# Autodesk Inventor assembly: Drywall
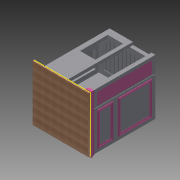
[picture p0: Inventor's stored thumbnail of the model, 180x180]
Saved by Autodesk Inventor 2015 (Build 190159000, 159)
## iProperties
Created: 2015-04
Part Number: Drywall
Document SubType Name: Assembly
Designer: suporte
_SolveAssemblyDoc: Frame Generator Solve Assembly
_Version: 15.0.0
Author: suporte
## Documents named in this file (69)
- C:\Users\suporte\Desktop\Kévin\WorldSkills SP\Grupo Kazuo\21\Arquivos Edição\Arquivos Inventor\Drywall.iam
- C:\Users\suporte\Desktop\Kévin\WorldSkills SP\Grupo Kazuo\21\Arquivos Edição\Arquivos Inventor\Base.ipt
- C:\Users\suporte\Desktop\Kévin\WorldSkills SP\Grupo Kazuo\21\Arquivos Edição\Arquivos Inventor\Moldura 1.ipt
- C:\Users\suporte\Desktop\Kévin\WorldSkills SP\Grupo Kazuo\21\Arquivos Edição\Arquivos Inventor\Moldura 2.ipt
- C:\Users\suporte\Desktop\Kévin\WorldSkills SP\Grupo Kazuo\21\Arquivos Edição\Arquivos Inventor\Rodapé.ipt
- C:\Users\suporte\Desktop\Kévin\WorldSkills SP\Grupo Kazuo\21\Arquivos Edição\Arquivos Inventor\Estrutura Metálica.ipt
- C:\Users\suporte\Desktop\Kévin\WorldSkills SP\Grupo Kazuo\21\Arquivos Edição\Arquivos Inventor\Drywall\Frame\Frame0001.iam
- C:\Users\suporte\Desktop\Kévin\WorldSkills SP\Grupo Kazuo\21\Arquivos Edição\Arquivos Inventor\Canto Madeira.ipt
- C:\Users\suporte\Desktop\Kévin\WorldSkills SP\Grupo Kazuo\21\Arquivos Edição\Arquivos Inventor\Canto Madeira 2.ipt
- C:\Users\suporte\Desktop\Kévin\WorldSkills SP\Grupo Kazuo\21\Arquivos Edição\Arquivos Inventor\Placa 1.ipt
- C:\Users\suporte\Desktop\Kévin\WorldSkills SP\Grupo Kazuo\21\Arquivos Edição\Arquivos Inventor\Placa 2.ipt
- C:\Users\suporte\Desktop\Kévin\WorldSkills SP\Grupo Kazuo\21\Arquivos Edição\Arquivos Inventor\Placa 3.ipt
- C:\Users\suporte\Desktop\Kévin\WorldSkills SP\Grupo Kazuo\21\Arquivos Edição\Arquivos Inventor\Placa 4.ipt
- C:\Users\suporte\Desktop\Kévin\WorldSkills SP\Grupo Kazuo\21\Arquivos Edição\Arquivos Inventor\Placa 5.ipt
- C:\Users\suporte\Desktop\Kévin\WorldSkills SP\Grupo Kazuo\21\Arquivos Edição\Arquivos Inventor\Placa 6.ipt
- C:\Users\suporte\Desktop\Kévin\WorldSkills SP\Grupo Kazuo\21\Arquivos Edição\Arquivos Inventor\Placa 7.ipt
- C:\Users\suporte\Desktop\Kévin\WorldSkills SP\Grupo Kazuo\21\Arquivos Edição\Arquivos Inventor\Placa 8.ipt
- C:\Users\suporte\Desktop\Kévin\WorldSkills SP\Grupo Kazuo\21\Arquivos Edição\Arquivos Inventor\Placa 9.ipt
- C:\Users\suporte\Desktop\Kévin\WorldSkills SP\Grupo Kazuo\21\Arquivos Edição\Arquivos Inventor\Placa 10.ipt
- C:\Users\suporte\Desktop\Kévin\WorldSkills SP\Grupo Kazuo\21\Arquivos Edição\Arquivos Inventor\Placa 11.ipt
- C:\Users\suporte\Desktop\Kévin\WorldSkills SP\Grupo Kazuo\21\Arquivos Edição\Arquivos Inventor\Placa 12.ipt
- C:\Users\suporte\Desktop\Kévin\WorldSkills SP\Grupo Kazuo\21\Arquivos Edição\Arquivos Inventor\Placa 13.ipt
- C:\Users\suporte\Desktop\Kévin\WorldSkills SP\Grupo Kazuo\21\Arquivos Edição\Arquivos Inventor\Placa 14.ipt
- C:\Users\suporte\Desktop\Kévin\WorldSkills SP\Grupo Kazuo\21\Arquivos Edição\Arquivos Inventor\Placa 15.ipt
- C:\Users\suporte\Desktop\Kévin\WorldSkills SP\Grupo Kazuo\21\Arquivos Edição\Arquivos Inventor\Placa 16.ipt
- C:\Users\suporte\Desktop\Kévin\WorldSkills SP\Grupo Kazuo\21\Arquivos Edição\Arquivos Inventor\Placa 18.ipt
- C:\Users\suporte\Desktop\Kévin\WorldSkills SP\Grupo Kazuo\21\Arquivos Edição\Arquivos Inventor\Placa 19.ipt
- C:\Users\suporte\Desktop\Kévin\WorldSkills SP\Grupo Kazuo\21\Arquivos Edição\Arquivos Inventor\Placa 20.ipt
- C:\Users\suporte\Desktop\Kévin\WorldSkills SP\Grupo Kazuo\21\Arquivos Edição\Arquivos Inventor\Placa 21.ipt
- C:\Users\suporte\Desktop\Kévin\WorldSkills SP\Grupo Kazuo\21\Arquivos Edição\Arquivos Inventor\Placa 22.ipt
- C:\Users\suporte\Desktop\Kévin\WorldSkills SP\Grupo Kazuo\21\Arquivos Edição\Arquivos Inventor\Placa 23.ipt
- C:\Users\suporte\Desktop\Kévin\WorldSkills SP\Grupo Kazuo\21\Arquivos Edição\Arquivos Inventor\Placa 24.ipt
- C:\Users\suporte\Desktop\Kévin\WorldSkills SP\Grupo Kazuo\21\Arquivos Edição\Arquivos Inventor\Placa 25.ipt
- C:\Users\suporte\Desktop\Kévin\WorldSkills SP\Grupo Kazuo\21\Arquivos Edição\Arquivos Inventor\Placa 26.ipt
- C:\Users\suporte\Desktop\Kévin\WorldSkills SP\Grupo Kazuo\21\Arquivos Edição\Arquivos Inventor\Placa 27.ipt
- C:\Users\suporte\Desktop\Kévin\WorldSkills SP\Grupo Kazuo\21\Arquivos Edição\Arquivos Inventor\Placa Lã 1.ipt
- C:\Users\suporte\Desktop\Kévin\WorldSkills SP\Grupo Kazuo\21\Arquivos Edição\Arquivos Inventor\Placa Lã 2.ipt
- C:\Users\suporte\Desktop\Kévin\WorldSkills SP\Grupo Kazuo\21\Arquivos Edição\Arquivos Inventor\Placa Lã 3.ipt
- C:\Users\suporte\Desktop\Kévin\WorldSkills SP\Grupo Kazuo\21\Arquivos Edição\Arquivos Inventor\Frame Bearing.ipt
- C:\Users\suporte\Desktop\Kévin\WorldSkills SP\Grupo Kazuo\21\Arquivos Edição\Arquivos Inventor\Placa Lã 4.ipt
- C:\Users\suporte\Desktop\Kévin\WorldSkills SP\Grupo Kazuo\21\Arquivos Edição\Arquivos Inventor\Placa 28.ipt
- C:\Users\suporte\Desktop\Kévin\WorldSkills SP\Grupo Kazuo\21\Arquivos Edição\Arquivos Inventor\Placa 29.ipt
- C:\Users\suporte\Desktop\Kévin\WorldSkills SP\Grupo Kazuo\21\Arquivos Edição\Arquivos Inventor\Placa 30.ipt
- C:\Users\suporte\Desktop\Kévin\WorldSkills SP\Grupo Kazuo\21\Arquivos Edição\Arquivos Inventor\Placa 31.ipt
- C:\Users\suporte\Desktop\Kévin\WorldSkills SP\Grupo Kazuo\21\Arquivos Edição\Arquivos Inventor\Placa 32.ipt
- C:\Users\suporte\Desktop\Kévin\WorldSkills SP\Grupo Kazuo\21\Arquivos Edição\Arquivos Inventor\Placa 33.ipt
- C:\Users\suporte\Desktop\Kévin\WorldSkills SP\Grupo Kazuo\21\Arquivos Edição\Arquivos Inventor\Placa 34.ipt
- C:\Users\suporte\Desktop\Kévin\WorldSkills SP\Grupo Kazuo\21\Arquivos Edição\Arquivos Inventor\Placa 35.ipt
- C:\Users\suporte\Desktop\Kévin\WorldSkills SP\Grupo Kazuo\21\Arquivos Edição\Arquivos Inventor\Placa 36.ipt
- C:\Users\suporte\Desktop\Kévin\WorldSkills SP\Grupo Kazuo\21\Arquivos Edição\Arquivos Inventor\Detalhe Pintado.ipt
- C:\Users\suporte\Desktop\Kévin\WorldSkills SP\Grupo Kazuo\21\Arquivos Edição\Arquivos Inventor\Placa Teto.ipt
- C:\Users\suporte\Desktop\Kévin\WorldSkills SP\Grupo Kazuo\21\Arquivos Edição\Arquivos Inventor\Placa 37.ipt
- C:\Users\suporte\Desktop\Kévin\WorldSkills SP\Grupo Kazuo\21\Arquivos Edição\Arquivos Inventor\Placa 38.ipt
- C:\Users\suporte\Desktop\Kévin\WorldSkills SP\Grupo Kazuo\21\Arquivos Edição\Arquivos Inventor\Placa 39.ipt
- C:\Users\suporte\Desktop\Kévin\WorldSkills SP\Grupo Kazuo\21\Arquivos Edição\Arquivos Inventor\Placa 40.ipt
- C:\Users\suporte\Desktop\Kévin\WorldSkills SP\Grupo Kazuo\21\Arquivos Edição\Arquivos Inventor\Placa 42.ipt
- C:\Users\suporte\Desktop\Kévin\WorldSkills SP\Grupo Kazuo\21\Arquivos Edição\Arquivos Inventor\Placa 43.ipt
- C:\Users\suporte\Desktop\Kévin\WorldSkills SP\Grupo Kazuo\21\Arquivos Edição\Arquivos Inventor\Placa 44.ipt
- C:\Users\suporte\Desktop\Kévin\WorldSkills SP\Grupo Kazuo\21\Arquivos Edição\Arquivos Inventor\Placa 45.ipt
- C:\Users\suporte\Desktop\Kévin\WorldSkills SP\Grupo Kazuo\21\Arquivos Edição\Arquivos Inventor\Placa 46.ipt
- C:\Users\suporte\Desktop\Kévin\WorldSkills SP\Grupo Kazuo\21\Arquivos Edição\Arquivos Inventor\Placa 47.ipt
- C:\Users\suporte\Desktop\Kévin\WorldSkills SP\Grupo Kazuo\21\Arquivos Edição\Arquivos Inventor\Placa 48.ipt
- C:\Users\suporte\Desktop\Kévin\WorldSkills SP\Grupo Kazuo\21\Arquivos Edição\Arquivos Inventor\Placa 49.ipt
- C:\Users\suporte\Desktop\Kévin\WorldSkills SP\Grupo Kazuo\21\Arquivos Edição\Arquivos Inventor\Placa 50.ipt
- C:\Users\suporte\Desktop\Kévin\WorldSkills SP\Grupo Kazuo\21\Arquivos Edição\Arquivos Inventor\Placa 51.ipt
- C:\Users\suporte\Desktop\Kévin\WorldSkills SP\Grupo Kazuo\21\Arquivos Edição\Arquivos Inventor\placa 52.ipt
- C:\Users\suporte\Desktop\Kévin\WorldSkills SP\Grupo Kazuo\21\Arquivos Edição\Arquivos Inventor\placa 53.ipt
- C:\Users\suporte\Desktop\Kévin\WorldSkills SP\Grupo Kazuo\21\Arquivos Edição\Arquivos Inventor\Placa 54.ipt
- C:\Users\suporte\Desktop\Kévin\WorldSkills SP\Grupo Kazuo\21\Arquivos Edição\Arquivos Inventor\Placa 55.ipt
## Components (87 placed, 68 different names)
1. Base:1 — Mate:2, Mate:3, Mate:4, Mate:5, Flush:4, Flush:5, Mate:6, Mate:7, Flush:6, Flush:7, Flush:8, Flush:9, Flush:13, Mate:8, Flush:15, Mate:11, Flush:18, Flush:19, Flush:32, Flush:33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
2. Moldura 1:1 — Flush:1, Flush:2, Mate:1, Flush:4
3. Moldura 2:1 — Flush:1, Flush:2, Mate:1, Flush:3, Mate:5
4. Rodapé:1 — Mate:2, Mate:3, Mate:4, Flush:3, Mate:76
5. Estrutura Metálica:1 — Flush:5, Mate:6, Mate:7, Mate:78
6. Frame0001:1 [sub-assembly] — Flush:10, Flush:11, Flush:12, Mate:9, Flush:14, Mate:12, Flush:16, Flush:17, Mate:15, Mate:17, Flush:22, Mate:18, Flush:27, Flush:28, Mate:22, Flush:30, Mate:25, Mate:28, Mate:30, Mate:32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
7. Canto Madeira:1 — Flush:6, Flush:7, Mate:33, Mate:34, Mate:35
8. Canto Madeira 2:1 — Flush:8, Flush:9
9. Placa 1:1 — Flush:10, Flush:11, Mate:14, Flush:20, Flush:21, Flush:24, Mate:20, Mate:23, Mate:24
10. Placa 2:1 — Flush:12, Flush:13, Mate:10, Mate:14, Flush:20, Flush:21
11. Placa 1:2 — Mate:8, Mate:9, Mate:10, Mate:13, Mate:27
12. Placa 3:1 — Flush:14, Flush:15, Mate:16, Flush:26, Mate:19, Mate:20
13. Placa 3:2 — Mate:11, Mate:12, Mate:13, Mate:29
14. Placa 4:1 — Flush:16, Flush:17, Mate:15, Mate:16, Mate:17, Flush:23, Mate:21
15. Placa 5:1 — Flush:18, Flush:19, Flush:25, Flush:26, Mate:19, Mate:31
16. Placa 6:1 — Flush:22, Flush:23, Flush:24
17. Placa 6:2 — Flush:25, Mate:18, Mate:21, Flush:29
18. Placa 7:1 — Flush:27, Flush:28, Mate:22, Flush:29, Mate:23, Flush:31, Mate:26
19. Placa 8:1 — Flush:30, Flush:31, Mate:24
20. Placa 8:2 — Mate:25, Mate:26, Mate:27
21. Placa 9:1 — Flush:32, Flush:33, Mate:30, Mate:31, Mate:37
22. Placa 10:1 — Flush:34, Flush:35, Mate:28, Mate:29, Mate:35
23. Placa 11:1 — Flush:36, Flush:37, Mate:32, Mate:33, Mate:34
24. Placa 12:1 — Flush:38, Flush:39, Mate:36, Mate:38, Mate:44, Flush:58
25. Placa 13:1 — Flush:40, Flush:41, Mate:37, Mate:40, Flush:47, Flush:48
26. Placa 14:1 — Flush:42, Flush:43, Mate:38, Mate:39
27. Placa 15:1 — Flush:44, Flush:45, Mate:40
28. Placa 16:1 — Flush:46, Flush:47, Flush:48
29. Placa 18:1 — Flush:51, Flush:52, Mate:41, Flush:54, Flush:57
30. Placa 19:1 — Flush:55, Flush:56, Mate:42, Flush:57, Flush:62, Mate:47
31. Placa 16:2 — Mate:43, Mate:44, Flush:58, Mate:46, Flush:59
32. Placa 19:2 — Mate:45, Mate:46, Flush:59, Mate:50
33. Placa 20:1 — Flush:60, Flush:61, Flush:62, Mate:47, Mate:79, Mate:87
34. Placa 21:1 — Flush:63, Flush:64, Mate:48, Flush:67, Mate:54, Mate:80, Mate:86
35. Placa 22:1 — Flush:65, Flush:66, Mate:49, Mate:50, Mate:52
36. Placa 23:1 — Flush:68, Flush:69, Mate:51, Mate:52
37. Placa 24:1 — Flush:70, Flush:71, Flush:72, Mate:53, Flush:75, Flush:140, Flush:141
38. Placa 25:1 — Flush:73, Flush:74, Mate:54, Flush:75
39. Placa 26:1 — Flush:76, Flush:77, Mate:56, Flush:80, Mate:58, Mate:74, Flush:118
40. Placa 26:2 — Mate:55, Flush:78, Flush:79, Mate:57, Flush:83, Mate:69, Flush:112
41. Placa 27:1 — Flush:81, Flush:82, Mate:58, Flush:85
42. Placa 27:2 — Mate:57, Flush:83, Flush:84, Mate:71, Flush:113, Mate:75
43. Placa Lã 1:1 — Flush:86, Flush:87
44. Placa Lã 2:1 — Flush:88, Flush:89
45. Placa Lã 3:1 — Flush:90, Flush:91
46. Frame Bearing:1 — Flush:92, Flush:93, Flush:94
47. Frame Bearing:2 — Mate:59, Mate:60, Flush:94, Mate:62, Mate:63
48. Placa Lã 4:1 — Flush:95, Flush:96
49. Placa 28:1 — Flush:97
50. Placa 28:2 — Mate:61, Mate:62, Mate:63
51. Placa 29:1 — Flush:98, Flush:99
52. Placa 30:1 — Flush:100, Flush:101
53. Placa 31:1 — Flush:102, Flush:103
54. Placa 32:1 — Flush:104, Flush:105
55. Placa 33:1 — Flush:106, Flush:107
56. Placa 34:1 — Flush:108, Flush:109, Flush:122, Flush:123
57. Placa 30:2 — Mate:66
58. Placa 31:2 — Mate:68, Mate:69, Flush:112
59. Placa 34:2 — Mate:70, Mate:71, Flush:113, Mate:73, Flush:114
60. Placa 33:2 — Mate:72, Mate:73, Flush:114
61. Placa 35:1 — Flush:115, Flush:116, Flush:117, Mate:74, Flush:118, Flush:120, Flush:121
62. Placa 36:1 — Flush:119, Flush:120, Flush:121
63. Detalhe Pintado:1 — Flush:122, Flush:123, Mate:75, Mate:76
64. Placa Teto:1 — Mate:77, Flush:124, Flush:125
65. Placa 37:1 — Flush:124, Flush:125, Flush:126, Flush:127, Flush:134, Flush:135, Flush:136, Flush:137
66. Placa 38:1 — Flush:126, Flush:127, Flush:128, Flush:129, Flush:132, Flush:133, Flush:138, Flush:139
67. Placa 39:1 — Flush:128, Flush:129, Flush:130, Flush:131
68. Placa 40:1 — Flush:130, Flush:131
69. Placa 42:1 — Flush:132, Flush:133
70. Placa 43:1 — Flush:134, Flush:135
71. Placa 44:1 — Flush:136, Flush:137
72. Placa 45:1 — Flush:138, Flush:139
73. Placa 46:1 — Flush:140, Flush:141, Flush:142, Flush:143, Flush:144, Flush:145, Flush:147
74. Placa 47:1 — Flush:142, Flush:143, Flush:148, Flush:149, Flush:152, Flush:153, Flush:154, Flush:155
75. Placa 48:1 — Flush:144, Flush:145, Flush:146
76. Placa 49:1 — Flush:146, Flush:147
77. Placa 50:1 — Flush:148, Flush:149, Flush:150, Flush:151
78. Placa 51:1 — Flush:150, Flush:151
79. placa 52:1 — Flush:152, Flush:153
80. placa 53:1 — Flush:154, Flush:155, Flush:156, Flush:157, Flush:158, Flush:159
81. Placa 54:1 — Flush:156, Flush:157
82. Placa 55:1 — Flush:158, Flush:159, Mate:81
83. placa 53:2 — Mate:79, Mate:80, Mate:81, Mate:88
84. placa 53:3 — Mate:82, Flush:160, Flush:161, Mate:83, Flush:162, Flush:163, Mate:88
85. placa 53:4 — Mate:85, Flush:163, Flush:164, Mate:86, Mate:87
86. Placa 54:2 — Mate:82, Flush:160, Flush:161, Mate:84
87. Placa 55:2 — Mate:83, Flush:162, Mate:84, Mate:85, Flush:164
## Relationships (244: Flush 159, Mate 85)
- Flush:1: Moldura 1:1 ↔ Moldura 2:1
- Flush:2: Moldura 1:1 ↔ Moldura 2:1
- Mate:1: Moldura 1:1 ↔ Moldura 2:1
- Mate:2: Base:1 ↔ Rodapé:1
- Mate:3: Base:1 ↔ Rodapé:1
- Mate:4: Base:1 ↔ Rodapé:1
- Flush:3: Moldura 2:1 ↔ Rodapé:1
- Mate:5: Base:1 ↔ Moldura 2:1
- Flush:4: Base:1 ↔ Moldura 1:1
- Flush:5: Base:1 ↔ Estrutura Metálica:1
- Mate:6: Base:1 ↔ Estrutura Metálica:1
- Mate:7: Base:1 ↔ Estrutura Metálica:1
- Flush:6: Base:1 ↔ Canto Madeira:1
- Flush:7: Base:1 ↔ Canto Madeira:1
- Flush:8: Base:1 ↔ Canto Madeira 2:1
- Flush:9: Base:1 ↔ Canto Madeira 2:1
- Flush:10: Frame0001:1 ↔ Placa 1:1
- Flush:11: Frame0001:1 ↔ Placa 1:1
- Flush:12: Frame0001:1 ↔ Placa 2:1
- Flush:13: Base:1 ↔ Placa 2:1
- Mate:8: Base:1 ↔ Placa 1:2
- Mate:9: Frame0001:1 ↔ Placa 1:2
- Mate:10: Placa 2:1 ↔ Placa 1:2
- Flush:14: Frame0001:1 ↔ Placa 3:1
- Flush:15: Base:1 ↔ Placa 3:1
- Mate:11: Base:1 ↔ Placa 3:2
- Mate:12: Frame0001:1 ↔ Placa 3:2
- Mate:13: Placa 1:2 ↔ Placa 3:2
- Flush:16: Frame0001:1 ↔ Placa 4:1
- Flush:17: Frame0001:1 ↔ Placa 4:1
- Flush:18: Base:1 ↔ Placa 5:1
- Flush:19: Base:1 ↔ Placa 5:1
- Mate:14: Placa 1:1 ↔ Placa 2:1
- Flush:20: Placa 1:1 ↔ Placa 2:1
- Flush:21: Placa 1:1 ↔ Placa 2:1
- Mate:15: Frame0001:1 ↔ Placa 4:1
- Mate:16: Placa 3:1 ↔ Placa 4:1
- Mate:17: Frame0001:1 ↔ Placa 4:1
- Flush:22: Frame0001:1 ↔ Placa 6:1
- Flush:23: Placa 4:1 ↔ Placa 6:1
- Flush:24: Placa 1:1 ↔ Placa 6:1
- Flush:25: Placa 5:1 ↔ Placa 6:2
- Mate:18: Frame0001:1 ↔ Placa 6:2
- Flush:26: Placa 3:1 ↔ Placa 5:1
- Mate:19: Placa 3:1 ↔ Placa 5:1
- Mate:20: Placa 1:1 ↔ Placa 3:1
- Mate:21: Placa 4:1 ↔ Placa 6:2
- Flush:27: Frame0001:1 ↔ Placa 7:1
- Flush:28: Frame0001:1 ↔ Placa 7:1
- Mate:22: Frame0001:1 ↔ Placa 7:1
- Flush:29: Placa 6:2 ↔ Placa 7:1
- Mate:23: Placa 1:1 ↔ Placa 7:1
- Flush:30: Frame0001:1 ↔ Placa 8:1
- Flush:31: Placa 7:1 ↔ Placa 8:1
- Mate:24: Placa 1:1 ↔ Placa 8:1
- Mate:25: Frame0001:1 ↔ Placa 8:2
- Mate:26: Placa 7:1 ↔ Placa 8:2
- Mate:27: Placa 1:2 ↔ Placa 8:2
- Flush:32: Base:1 ↔ Placa 9:1
- Flush:33: Base:1 ↔ Placa 9:1
- Flush:34: Base:1 ↔ Placa 10:1
- Flush:35: Base:1 ↔ Placa 10:1
- Mate:28: Frame0001:1 ↔ Placa 10:1
- Mate:29: Placa 3:2 ↔ Placa 10:1
- Mate:30: Frame0001:1 ↔ Placa 9:1
- Mate:31: Placa 5:1 ↔ Placa 9:1
- Flush:36: Base:1 ↔ Placa 11:1
- Flush:37: Base:1 ↔ Placa 11:1
- Mate:32: Frame0001:1 ↔ Placa 11:1
- Mate:33: Canto Madeira:1 ↔ Placa 11:1
- Mate:34: Canto Madeira:1 ↔ Placa 11:1
- Mate:35: Canto Madeira:1 ↔ Placa 10:1
- Flush:38: Frame0001:1 ↔ Placa 12:1
- Flush:39: Base:1 ↔ Placa 12:1
- Mate:36: Frame0001:1 ↔ Placa 12:1
- Flush:40: Frame0001:1 ↔ Placa 13:1
- Flush:41: Base:1 ↔ Placa 13:1
- Mate:37: Placa 9:1 ↔ Placa 13:1
- Flush:42: Base:1 ↔ Placa 14:1
- Flush:43: Base:1 ↔ Placa 14:1
- Mate:38: Placa 12:1 ↔ Placa 14:1
- Mate:39: Frame0001:1 ↔ Placa 14:1
- Flush:44: Frame0001:1 ↔ Placa 15:1
- Flush:45: Frame0001:1 ↔ Placa 15:1
- Mate:40: Placa 13:1 ↔ Placa 15:1
- Flush:46: Frame0001:1 ↔ Placa 16:1
- Flush:47: Placa 13:1 ↔ Placa 16:1
- Flush:48: Placa 13:1 ↔ Placa 16:1
- Flush:51: Base:1 ↔ Placa 18:1
- Flush:52: Base:1 ↔ Placa 18:1
- Mate:41: Frame0001:1 ↔ Placa 18:1
- Flush:54: Frame0001:1 ↔ Placa 18:1
- Flush:55: Base:1 ↔ Placa 19:1
- Flush:56: Base:1 ↔ Placa 19:1
- Mate:42: Frame0001:1 ↔ Placa 19:1
- Flush:57: Placa 18:1 ↔ Placa 19:1
- Mate:43: Frame0001:1 ↔ Placa 16:2
- Mate:44: Placa 12:1 ↔ Placa 16:2
- Flush:58: Placa 12:1 ↔ Placa 16:2
- Mate:45: Frame0001:1 ↔ Placa 19:2
- Mate:46: Placa 16:2 ↔ Placa 19:2
- Flush:59: Placa 16:2 ↔ Placa 19:2
- Flush:60: Base:1 ↔ Placa 20:1
- Flush:61: Base:1 ↔ Placa 20:1
- Flush:62: Placa 19:1 ↔ Placa 20:1
- Mate:47: Placa 19:1 ↔ Placa 20:1
- Flush:63: Base:1 ↔ Placa 21:1
- Flush:64: Base:1 ↔ Placa 21:1
- Flush:65: Base:1 ↔ Placa 22:1
- Flush:66: Base:1 ↔ Placa 22:1
- Mate:48: Frame0001:1 ↔ Placa 21:1
- Flush:67: Frame0001:1 ↔ Placa 21:1
- Mate:49: Frame0001:1 ↔ Placa 22:1
- Mate:50: Placa 19:2 ↔ Placa 22:1
- Flush:68: Base:1 ↔ Placa 23:1
- Flush:69: Base:1 ↔ Placa 23:1
- Mate:51: Frame0001:1 ↔ Placa 23:1
- Mate:52: Placa 22:1 ↔ Placa 23:1
- Flush:70: Base:1 ↔ Placa 24:1
- Flush:71: Base:1 ↔ Placa 24:1
- Flush:72: Frame0001:1 ↔ Placa 24:1
- Mate:53: Frame0001:1 ↔ Placa 24:1
- Flush:73: Base:1 ↔ Placa 25:1
- Flush:74: Base:1 ↔ Placa 25:1
- Mate:54: Placa 21:1 ↔ Placa 25:1
- Flush:75: Placa 24:1 ↔ Placa 25:1
- Flush:76: Base:1 ↔ Placa 26:1
- Flush:77: Base:1 ↔ Placa 26:1
- Mate:55: Frame0001:1 ↔ Placa 26:2
- Flush:78: Frame0001:1 ↔ Placa 26:2
- Flush:79: Frame0001:1 ↔ Placa 26:2
- Mate:56: Frame0001:1 ↔ Placa 26:1
- Flush:80: Frame0001:1 ↔ Placa 26:1
- Flush:81: Base:1 ↔ Placa 27:1
- Flush:82: Base:1 ↔ Placa 27:1
- Mate:57: Placa 26:2 ↔ Placa 27:2
- Flush:83: Placa 26:2 ↔ Placa 27:2
- Flush:84: Frame0001:1 ↔ Placa 27:2
- Mate:58: Placa 26:1 ↔ Placa 27:1
- Flush:85: Frame0001:1 ↔ Placa 27:1
- Flush:86: Base:1 ↔ Placa Lã 1:1
- Flush:87: Base:1 ↔ Placa Lã 1:1
- Flush:88: Base:1 ↔ Placa Lã 2:1
- Flush:89: Base:1 ↔ Placa Lã 2:1
- Flush:90: Base:1 ↔ Placa Lã 3:1
- Flush:91: Base:1 ↔ Placa Lã 3:1
- Flush:92: Base:1 ↔ Frame Bearing:1
- Flush:93: Base:1 ↔ Frame Bearing:1
- Mate:59: Frame0001:1 ↔ Frame Bearing:2
- Mate:60: Frame0001:1 ↔ Frame Bearing:2
- Flush:94: Frame Bearing:1 ↔ Frame Bearing:2
- Flush:95: Base:1 ↔ Placa Lã 4:1
- Flush:96: Base:1 ↔ Placa Lã 4:1
- Flush:97: Base:1 ↔ Placa 28:1
- Mate:61: Frame0001:1 ↔ Placa 28:2
- Mate:62: Frame Bearing:2 ↔ Placa 28:2
- Mate:63: Frame Bearing:2 ↔ Placa 28:2
- Flush:98: Base:1 ↔ Placa 29:1
- Flush:99: Base:1 ↔ Placa 29:1
- Flush:100: Base:1 ↔ Placa 30:1
- Flush:101: Base:1 ↔ Placa 30:1
- Flush:102: Base:1 ↔ Placa 31:1
- Flush:103: Base:1 ↔ Placa 31:1
- Flush:104: Base:1 ↔ Placa 32:1
- Flush:105: Base:1 ↔ Placa 32:1
- Flush:106: Base:1 ↔ Placa 33:1
- Flush:107: Base:1 ↔ Placa 33:1
- Flush:108: Base:1 ↔ Placa 34:1
- Flush:109: Base:1 ↔ Placa 34:1
- Mate:66: Base:1 ↔ Placa 30:2
- Mate:68: Base:1 ↔ Placa 31:2
- Mate:69: Placa 26:2 ↔ Placa 31:2
- Flush:112: Placa 26:2 ↔ Placa 31:2
- Mate:70: Base:1 ↔ Placa 34:2
- Mate:71: Placa 27:2 ↔ Placa 34:2
- Flush:113: Placa 27:2 ↔ Placa 34:2
- Mate:72: Base:1 ↔ Placa 33:2
- Mate:73: Placa 34:2 ↔ Placa 33:2
- Flush:114: Placa 34:2 ↔ Placa 33:2
- Flush:115: Base:1 ↔ Placa 35:1
- Flush:116: Base:1 ↔ Placa 35:1
- Flush:117: Frame0001:1 ↔ Placa 35:1
- Mate:74: Placa 26:1 ↔ Placa 35:1
- Flush:118: Placa 26:1 ↔ Placa 35:1
- Flush:119: Base:1 ↔ Placa 36:1
- Flush:120: Placa 35:1 ↔ Placa 36:1
- Flush:121: Placa 35:1 ↔ Placa 36:1
- Flush:122: Placa 34:1 ↔ Detalhe Pintado:1
- Flush:123: Placa 34:1 ↔ Detalhe Pintado:1
- Mate:75: Placa 27:2 ↔ Detalhe Pintado:1
- Mate:76: Rodapé:1 ↔ Detalhe Pintado:1
- Mate:77: Frame0001:1 ↔ Placa Teto:1
- Flush:124: Placa Teto:1 ↔ Placa 37:1
- Flush:125: Placa Teto:1 ↔ Placa 37:1
- Flush:126: Placa 37:1 ↔ Placa 38:1
- Flush:127: Placa 37:1 ↔ Placa 38:1
- Flush:128: Placa 38:1 ↔ Placa 39:1
- Flush:129: Placa 38:1 ↔ Placa 39:1
- Flush:130: Placa 39:1 ↔ Placa 40:1
- Flush:131: Placa 39:1 ↔ Placa 40:1
- Flush:132: Placa 38:1 ↔ Placa 42:1
- Flush:133: Placa 38:1 ↔ Placa 42:1
- Flush:134: Placa 37:1 ↔ Placa 43:1
- Flush:135: Placa 37:1 ↔ Placa 43:1
- Flush:136: Placa 37:1 ↔ Placa 44:1
- Flush:137: Placa 37:1 ↔ Placa 44:1
- Flush:138: Placa 38:1 ↔ Placa 45:1
- Flush:139: Placa 38:1 ↔ Placa 45:1
- Flush:140: Placa 24:1 ↔ Placa 46:1
- Flush:141: Placa 24:1 ↔ Placa 46:1
- Flush:142: Placa 46:1 ↔ Placa 47:1
- Flush:143: Placa 46:1 ↔ Placa 47:1
- Flush:144: Placa 46:1 ↔ Placa 48:1
- Flush:145: Placa 46:1 ↔ Placa 48:1
- Flush:146: Placa 48:1 ↔ Placa 49:1
- Flush:147: Placa 46:1 ↔ Placa 49:1
- Flush:148: Placa 47:1 ↔ Placa 50:1
- Flush:149: Placa 47:1 ↔ Placa 50:1
- Flush:150: Placa 50:1 ↔ Placa 51:1
- Flush:151: Placa 50:1 ↔ Placa 51:1
- Flush:152: Placa 47:1 ↔ placa 52:1
- Flush:153: Placa 47:1 ↔ placa 52:1
- Mate:78: Estrutura Metálica:1 ↔ Frame0001:1
- Flush:154: Placa 47:1 ↔ placa 53:1
- Flush:155: Placa 47:1 ↔ placa 53:1
- Flush:156: placa 53:1 ↔ Placa 54:1
- Flush:157: placa 53:1 ↔ Placa 54:1
- Flush:158: placa 53:1 ↔ Placa 55:1
- Flush:159: placa 53:1 ↔ Placa 55:1
- Mate:79: Placa 20:1 ↔ placa 53:2
- Mate:80: Placa 21:1 ↔ placa 53:2
- Mate:81: Placa 55:1 ↔ placa 53:2
- Mate:82: placa 53:3 ↔ Placa 54:2
- Flush:160: placa 53:3 ↔ Placa 54:2
- Flush:161: placa 53:3 ↔ Placa 54:2
- Mate:83: placa 53:3 ↔ Placa 55:2
- Flush:162: placa 53:3 ↔ Placa 55:2
- Mate:84: Placa 54:2 ↔ Placa 55:2
- Mate:85: placa 53:4 ↔ Placa 55:2
- Flush:163: placa 53:3 ↔ placa 53:4
- Flush:164: placa 53:4 ↔ Placa 55:2
- Mate:86: Placa 21:1 ↔ placa 53:4
- Mate:87: Placa 20:1 ↔ placa 53:4
- Mate:88: placa 53:2 ↔ placa 53:3
